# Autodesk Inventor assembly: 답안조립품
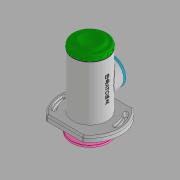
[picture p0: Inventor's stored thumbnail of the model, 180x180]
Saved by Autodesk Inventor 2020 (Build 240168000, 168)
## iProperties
Created: 2022-05
Part Number: 답안조립품
Document SubType Name: Assembly
Designer: Student
Author: Student
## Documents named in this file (18)
- C:\Users\Student\Desktop\720506V1019\답안조립품.iam
- C:\Users\Student\Desktop\720506V1019\본체.ipt
- C:\Users\Student\Desktop\720506V1019\개스킷.ipt
- C:\Users\Student\Desktop\720506V1019\사이드 커버.ipt
- 사이드 커버.ipt
- C:\Users\Student\Desktop\720506V1019\탑 커버.ipt
- C:\Users\Student\Desktop\720506V1019\베어링 6202.ipt
- C:\Users\Student\Desktop\720506V1019\축.ipt
- C:\Users\Student\Desktop\720506V1019\부시1.ipt
- C:\Users\Student\Desktop\720506V1019\오일 실 15 x 30 x 7.ipt
- C:\Users\Student\Desktop\720506V1019\멈춤링 35 x 1.6.ipt
- C:\Users\Student\Desktop\720506V1019\부시2.ipt
- C:\Users\Student\Desktop\720506V1019\와셔 10 x 21.ipt
- C:\Users\Student\Desktop\720506V1019\너트 M10.ipt
- C:\Users\Student\Desktop\720506V1019\키 4 x 4.ipt
- C:\Users\Student\Desktop\720506V1019\V-벨트풀리.ipt
- C:\Users\Student\Desktop\720506V1019\와셔 4 x 16.ipt
- C:\Users\Student\Desktop\720506V1019\볼트 M4 x 10.ipt
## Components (3 placed, 3 different names)
1. 개스킷:1
2. V-벨트풀리:1
3. ISO 4017 M4 x 10:1
